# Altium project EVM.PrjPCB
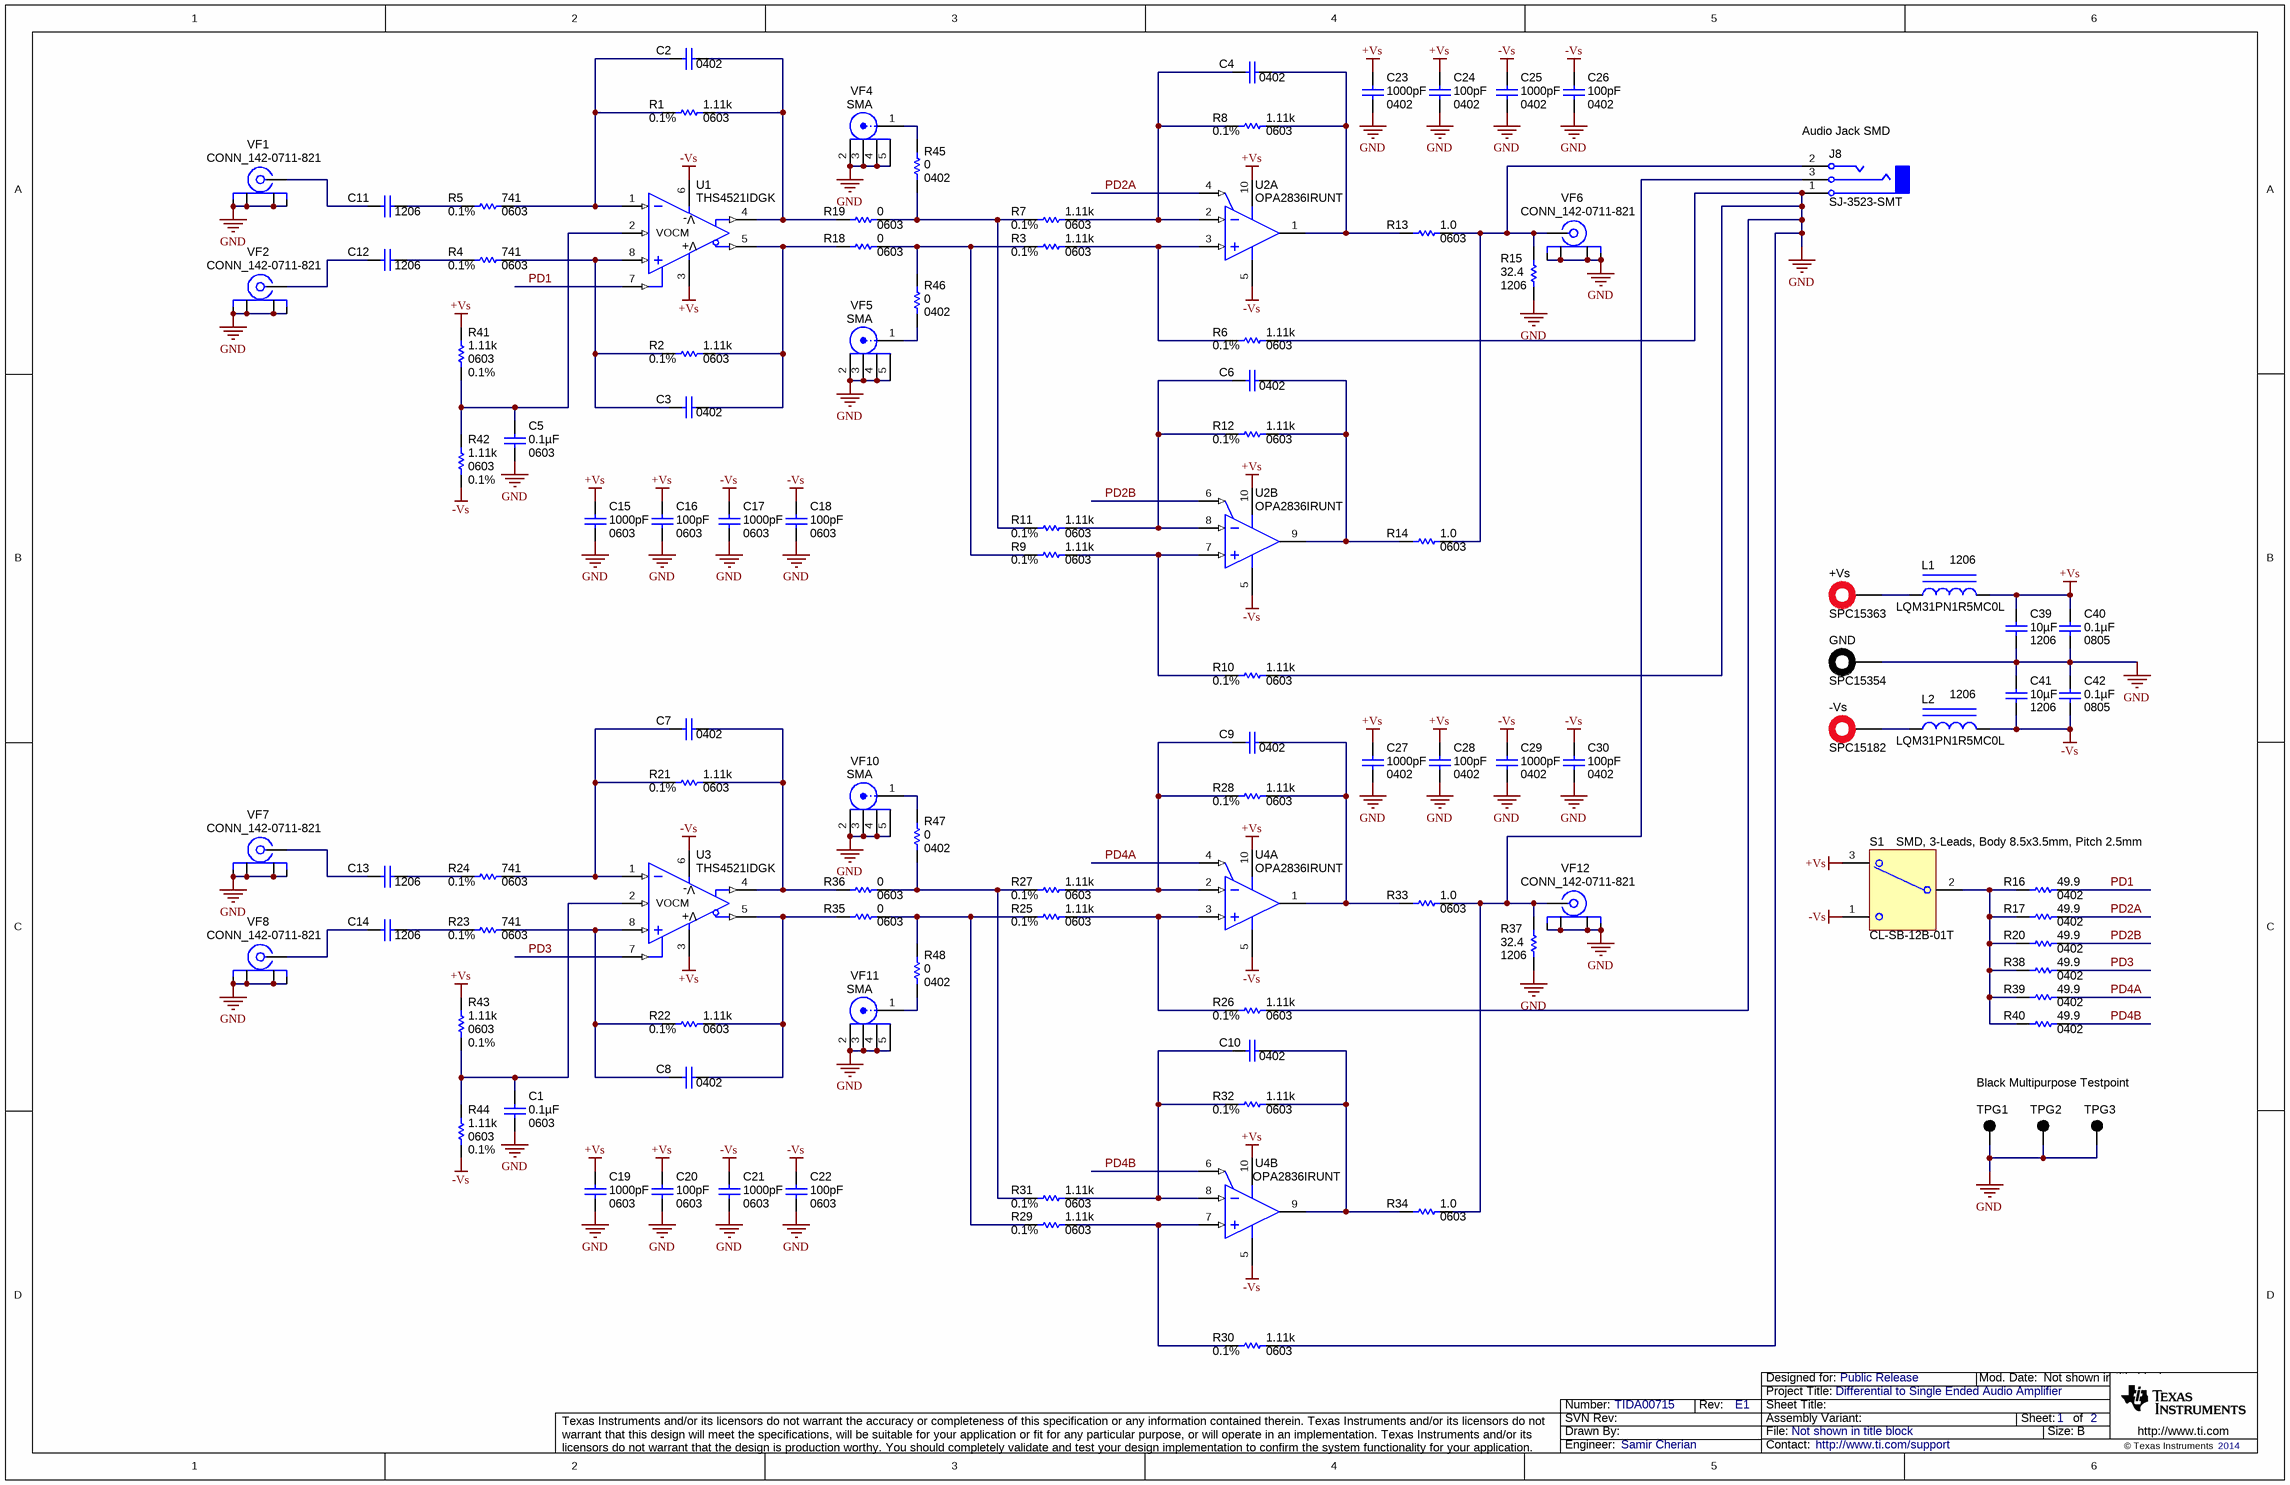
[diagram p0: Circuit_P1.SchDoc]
TechSupport: http://www.ti.com/support; SCH_Rev: E1; PRJ_Title: Differential to Single Ended Audio Amplifier; PRJ_Number: TIDA00715; PRJ_Engineer: Samir Cherian; PRJ_Customer: Public Release; PCB_Rev: E1; PCB_Layout: Bob Holtz; CopyrightYear: 2014
2 sheets, 126 parts. Net scope: global (net labels, ports and power ports of the same name join across sheets).
Board file: EVM.PcbDoc
Sheets:
  Circuit_P1.SchDoc
  Hardware_P2.SchDoc

## Sheet Circuit_P1.SchDoc
size 431 x 279 mm; Date: Not shown in title block; ApprovedBy: Not shown in title block; CheckedBy: Not shown in title block; Author: Not shown in title block; CompanyName: Not shown in title block; Engineer: Not shown in title block; Organization: Not shown in title block; Address1: Not shown in title block; Address2: Not shown in title block; Address3: Not shown in title block; Address4: Not shown in title block; DocumentNumber: 1; Revision: Use project parameter SCH_Rev; SheetNumber: 1; SheetTotal: 2; PageSetup: Record=PageOptions¦CenterHorizontal=True¦CenterVertical=True¦PrintScale=0.64¦XCorrection=1.00¦YCorrection=1.00¦PrintKind=0¦BorderSize=5000000¦LeftOffset=0¦BottomOffset=0¦Orientation=2¦PaperLength=1000¦PaperWidth=1000¦Scale=100¦PaperSource=15¦PrintQuality=600¦MediaType=1¦DitherType=10¦PrintScaleMode=1¦PaperKind=Letter

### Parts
+Vs  SPC15363  [Tenma_SPC15363]
-Vs  SPC15182  [Tenma_SPC15363]
C1  ValueDisplayed: 0.1µF  PackageReference: 0603  [0603L]  (hidden comment: C1608X7R1H104K)
C2  PackageReference: 0402  [0402L]
C3  PackageReference: 0402  [0402L]
C4  PackageReference: 0402  [0402L]
C5  ValueDisplayed: 0.1µF  PackageReference: 0603  [0603L]  (hidden comment: C1608X7R1H104K)
C6  PackageReference: 0402  [0402L]
C7  PackageReference: 0402  [0402L]
C8  PackageReference: 0402  [0402L]
C9  PackageReference: 0402  [0402L]
C10  PackageReference: 0402  [0402L]
C11  PackageReference: 1206  [1206L]
C12  PackageReference: 1206  [1206L]
C13  PackageReference: 1206  [1206L]
C14  PackageReference: 1206  [1206L]
C15  ValueDisplayed: 1000pF  PackageReference: 0603  [0603L]  (hidden comment: C1608C0G1H102J)
C16  ValueDisplayed: 100pF  PackageReference: 0603  [0603L]  (hidden comment: 06035A101JAT2A)
C17  ValueDisplayed: 1000pF  PackageReference: 0603  [0603L]  (hidden comment: C1608C0G1H102J)
C18  ValueDisplayed: 100pF  PackageReference: 0603  [0603L]  (hidden comment: 06035A101JAT2A)
C19  ValueDisplayed: 1000pF  PackageReference: 0603  [0603L]  (hidden comment: C1608C0G1H102J)
C20  ValueDisplayed: 100pF  PackageReference: 0603  [0603L]  (hidden comment: 06035A101JAT2A)
C21  ValueDisplayed: 1000pF  PackageReference: 0603  [0603L]  (hidden comment: C1608C0G1H102J)
C22  ValueDisplayed: 100pF  PackageReference: 0603  [0603L]  (hidden comment: 06035A101JAT2A)
C23  ValueDisplayed: 1000pF  PackageReference: 0402  [0402L]  (hidden comment: C1005C0G1E102J)
C24  ValueDisplayed: 100pF  PackageReference: 0402  [0402L]  (hidden comment: CC0402JRNPO9BN101)
C25  ValueDisplayed: 1000pF  PackageReference: 0402  [0402L]  (hidden comment: C1005C0G1E102J)
C26  ValueDisplayed: 100pF  PackageReference: 0402  [0402L]  (hidden comment: CC0402JRNPO9BN101)
C27  ValueDisplayed: 1000pF  PackageReference: 0402  [0402L]  (hidden comment: C1005C0G1E102J)
C28  ValueDisplayed: 100pF  PackageReference: 0402  [0402L]  (hidden comment: CC0402JRNPO9BN101)
C29  ValueDisplayed: 1000pF  PackageReference: 0402  [0402L]  (hidden comment: C1005C0G1E102J)
C30  ValueDisplayed: 100pF  PackageReference: 0402  [0402L]  (hidden comment: CC0402JRNPO9BN101)
C39  ValueDisplayed: 10µF  PackageReference: 1206  [1206L]  (hidden comment: GRM31CR61E106KA12L)
C40  ValueDisplayed: 0.1µF  PackageReference: 0805  [0805L]  (hidden comment: 08055C104KAT2A)
C41  ValueDisplayed: 10µF  PackageReference: 1206  [1206L]  (hidden comment: GRM31CR61E106KA12L)
C42  ValueDisplayed: 0.1µF  PackageReference: 0805  [0805L]  (hidden comment: 08055C104KAT2A)
GND  SPC15354  [Tenma_SPC15354]
J8  SJ-3523-SMT  PackageReference: Audio Jack SMD  [CUI_SJ-3523-SMT]
L1  LQM31PN1R5MC0L  PackageReference: 1206  [1206L]
L2  LQM31PN1R5MC0L  PackageReference: 1206  [1206L]
R1  ValueDisplayed: 1.11k  PackageReference: 0603  Value1: 0.1%  [0603L]  (hidden comment: RT0603BRD071K11L)
R2  ValueDisplayed: 1.11k  PackageReference: 0603  Value1: 0.1%  [0603L]  (hidden comment: RT0603BRD071K11L)
R3  ValueDisplayed: 1.11k  PackageReference: 0603  Value1: 0.1%  [0603L]  (hidden comment: RT0603BRD071K11L)
R4  ValueDisplayed: 741  PackageReference: 0603  Value1: 0.1%  [0603L]  (hidden comment: RT0603BRD07741RL)
R5  ValueDisplayed: 741  PackageReference: 0603  Value1: 0.1%  [0603L]  (hidden comment: RT0603BRD07741RL)
R6  ValueDisplayed: 1.11k  PackageReference: 0603  Value1: 0.1%  [0603L]  (hidden comment: RT0603BRD071K11L)
R7  ValueDisplayed: 1.11k  PackageReference: 0603  Value1: 0.1%  [0603L]  (hidden comment: RT0603BRD071K11L)
R8  ValueDisplayed: 1.11k  PackageReference: 0603  Value1: 0.1%  [0603L]  (hidden comment: RT0603BRD071K11L)
R9  ValueDisplayed: 1.11k  PackageReference: 0603  Value1: 0.1%  [0603L]  (hidden comment: RT0603BRD071K11L)
R10  ValueDisplayed: 1.11k  PackageReference: 0603  Value1: 0.1%  [0603L]  (hidden comment: RT0603BRD071K11L)
R11  ValueDisplayed: 1.11k  PackageReference: 0603  Value1: 0.1%  [0603L]  (hidden comment: RT0603BRD071K11L)
R12  ValueDisplayed: 1.11k  PackageReference: 0603  Value1: 0.1%  [0603L]  (hidden comment: RT0603BRD071K11L)
R13  ValueDisplayed: 1.0  PackageReference: 0603  [0603L]  (hidden comment: CRCW06031R00JNEA)
R14  ValueDisplayed: 1.0  PackageReference: 0603  [0603L]  (hidden comment: CRCW06031R00JNEA)
R15  ValueDisplayed: 32.4  PackageReference: 1206  [1206L]  (hidden comment: CRCW120632R4FKEA)
R16  ValueDisplayed: 49.9  PackageReference: 0402  [0402L]  (hidden comment: CRCW040249R9FKED)
R17  ValueDisplayed: 49.9  PackageReference: 0402  [0402L]  (hidden comment: CRCW040249R9FKED)
R18  ValueDisplayed: 0  PackageReference: 0603  [0603L]  (hidden comment: CRCW06030000Z0EA)
R19  ValueDisplayed: 0  PackageReference: 0603  [0603L]  (hidden comment: CRCW06030000Z0EA)
R20  ValueDisplayed: 49.9  PackageReference: 0402  [0402L]  (hidden comment: CRCW040249R9FKED)
R21  ValueDisplayed: 1.11k  PackageReference: 0603  Value1: 0.1%  [0603L]  (hidden comment: RT0603BRD071K11L)
R22  ValueDisplayed: 1.11k  PackageReference: 0603  Value1: 0.1%  [0603L]  (hidden comment: RT0603BRD071K11L)
R23  ValueDisplayed: 741  PackageReference: 0603  Value1: 0.1%  [0603L]  (hidden comment: RT0603BRD07741RL)
R24  ValueDisplayed: 741  PackageReference: 0603  Value1: 0.1%  [0603L]  (hidden comment: RT0603BRD07741RL)
R25  ValueDisplayed: 1.11k  PackageReference: 0603  Value1: 0.1%  [0603L]  (hidden comment: RT0603BRD071K11L)
R26  ValueDisplayed: 1.11k  PackageReference: 0603  Value1: 0.1%  [0603L]  (hidden comment: RT0603BRD071K11L)
R27  ValueDisplayed: 1.11k  PackageReference: 0603  Value1: 0.1%  [0603L]  (hidden comment: RT0603BRD071K11L)
R28  ValueDisplayed: 1.11k  PackageReference: 0603  Value1: 0.1%  [0603L]  (hidden comment: RT0603BRD071K11L)
R29  ValueDisplayed: 1.11k  PackageReference: 0603  Value1: 0.1%  [0603L]  (hidden comment: RT0603BRD071K11L)
R30  ValueDisplayed: 1.11k  PackageReference: 0603  Value1: 0.1%  [0603L]  (hidden comment: RT0603BRD071K11L)
R31  ValueDisplayed: 1.11k  PackageReference: 0603  Value1: 0.1%  [0603L]  (hidden comment: RT0603BRD071K11L)
R32  ValueDisplayed: 1.11k  PackageReference: 0603  Value1: 0.1%  [0603L]  (hidden comment: RT0603BRD071K11L)
R33  ValueDisplayed: 1.0  PackageReference: 0603  [0603L]  (hidden comment: CRCW06031R00JNEA)
R34  ValueDisplayed: 1.0  PackageReference: 0603  [0603L]  (hidden comment: CRCW06031R00JNEA)
R35  ValueDisplayed: 0  PackageReference: 0603  [0603L]  (hidden comment: CRCW06030000Z0EA)
R36  ValueDisplayed: 0  PackageReference: 0603  [0603L]  (hidden comment: CRCW06030000Z0EA)
R37  ValueDisplayed: 32.4  PackageReference: 1206  [1206L]  (hidden comment: CRCW120632R4FKEA)
R38  ValueDisplayed: 49.9  PackageReference: 0402  [0402L]  (hidden comment: CRCW040249R9FKED)
R39  ValueDisplayed: 49.9  PackageReference: 0402  [0402L]  (hidden comment: CRCW040249R9FKED)
R40  ValueDisplayed: 49.9  PackageReference: 0402  [0402L]  (hidden comment: CRCW040249R9FKED)
R41  ValueDisplayed: 1.11k  PackageReference: 0603  Value1: 0.1%  [0603L]  (hidden comment: RT0603BRD071K11L)
R42  ValueDisplayed: 1.11k  PackageReference: 0603  Value1: 0.1%  [0603L]  (hidden comment: RT0603BRD071K11L)
R43  ValueDisplayed: 1.11k  PackageReference: 0603  Value1: 0.1%  [0603L]  (hidden comment: RT0603BRD071K11L)
R44  ValueDisplayed: 1.11k  PackageReference: 0603  Value1: 0.1%  [0603L]  (hidden comment: RT0603BRD071K11L)
R45  ValueDisplayed: 0  PackageReference: 0402  [0402L]  (hidden comment: CRCW04020000Z0ED)
R46  ValueDisplayed: 0  PackageReference: 0402  [0402L]  (hidden comment: CRCW04020000Z0ED)
R47  ValueDisplayed: 0  PackageReference: 0402  [0402L]  (hidden comment: CRCW04020000Z0ED)
R48  ValueDisplayed: 0  PackageReference: 0402  [0402L]  (hidden comment: CRCW04020000Z0ED)
S1  CL-SB-12B-01T  PackageReference: SMD, 3-Leads, Body 8.5x3.5mm, Pitch 2.5mm  [SW_CL-SB-12B-01]
TPG1  5011  [Keystone5011]  (value not drawn)
TPG2  PackageReference: Black Multipurpose Testpoint  [Keystone5011]  (hidden comment: 5011)
TPG3  5011  [Keystone5011]  (value not drawn)
U1  THS4521IDGK  [DGK0008A_N]
U2  OPA2836IRUNT  [RUN0010A]  (parts A,B of 2)
U3  THS4521IDGK  [DGK0008A_N]
U4  OPA2836IRUNT  [RUN0010A]  (parts A,B of 2)
VF1  CONN_142-0711-821  [CONN_142-0711-821]
VF2  CONN_142-0711-821  [CONN_142-0711-821]
VF4  PackageReference: SMA  [Johnson_142-0701-20x]  (hidden comment: 142-0701-201)
VF5  PackageReference: SMA  [Johnson_142-0701-20x]  (hidden comment: 142-0701-201)
VF6  CONN_142-0711-821  [CONN_142-0711-821]
VF7  CONN_142-0711-821  [CONN_142-0711-821]
VF8  CONN_142-0711-821  [CONN_142-0711-821]
VF10  PackageReference: SMA  [Johnson_142-0701-20x]  (hidden comment: 142-0701-201)
VF11  PackageReference: SMA  [Johnson_142-0701-20x]  (hidden comment: 142-0701-201)
VF12  CONN_142-0711-821  [CONN_142-0711-821]

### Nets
+Vs: C15.1 C16.1 C19.1 C20.1 C23.1 C24.1 C27.1 C28.1 C39.1 C40.1 L1.2 R41.2 R43.2 S1.3 U1.3(VS+) U2.10(VS+) U3.3(VS+) U4.10(VS+)
-Vs: C17.1 C18.1 C21.1 C22.1 C25.1 C26.1 C29.1 C30.1 C41.2 C42.2 L2.2 R42.1 R44.1 S1.1 U1.6(VS-) U2.5(VS-) U3.6(VS-) U4.5(VS-)
GND: C1.2 C5.2 C15.2 C16.2 C17.2 C18.2 C19.2 C20.2 C21.2 C22.2 C23.2 C24.2 C25.2 C26.2 C27.2 C28.2 C29.2 C30.2 C39.2 C40.2 C41.1 C42.1 GND.1 J8.1(SLEEVE) R6.2 R10.2 R15.1 R26.2 R30.2 R37.1 TPG1.1 TPG2.1 TPG3.1 VF1.2(GND) VF1.3(GND) VF1.4 VF1.5(GND) VF2.2(GND) VF2.3(GND) VF2.4 VF2.5(GND) VF4.2 VF4.3 VF4.4 VF4.5 VF5.2 VF5.3 VF5.4 VF5.5 VF6.2(GND) VF6.3(GND) VF6.4 VF6.5(GND) VF7.2(GND) VF7.3(GND) VF7.4 VF7.5(GND) VF8.2(GND) VF8.3(GND) VF8.4 VF8.5(GND) VF10.2 VF10.3 VF10.4 VF10.5 VF11.2 VF11.3 VF11.4 VF11.5 VF12.2(GND) VF12.3(GND) VF12.4 VF12.5(GND)
PD1: R16.2 U1.7(~{PD})
PD2A: R17.2 U2.4(~{PD1})
PD2B: R20.2 U2.6(~{PD2})
PD3: R38.2 U3.7(~{PD})
PD4A: R39.2 U4.4(~{PD1})
PD4B: R40.2 U4.6(~{PD2})
Net+Vs_1: +Vs.1 L1.1
Net-Vs_1: -Vs.1 L2.1
NetC1_1: C1.1 R43.1 R44.2 U3.2(VOCM)
NetC2_1: C2.1 R1.2 R19.1 U1.4(VOUT+)
NetC2_2: C2.2 R1.1 R5.2 U1.1(VIN-)
NetC3_1: C3.1 R2.2 R18.1 U1.5(VOUT-)
NetC3_2: C3.2 R2.1 R4.2 U1.8(VIN+)
NetC4_1: C4.1 R8.2 R13.1 U2.1(VOUT1)
NetC4_2: C4.2 R7.2 R8.1 U2.2(VIN1-)
NetC5_1: C5.1 R41.1 R42.2 U1.2(VOCM)
NetC6_1: C6.1 R12.2 R14.1 U2.9(VOUT2)
NetC6_2: C6.2 R11.2 R12.1 U2.8(VIN2-)
NetC7_1: C7.1 R21.2 R36.1 U3.4(VOUT+)
NetC7_2: C7.2 R21.1 R24.2 U3.1(VIN-)
NetC8_1: C8.1 R22.2 R35.1 U3.5(VOUT-)
NetC8_2: C8.2 R22.1 R23.2 U3.8(VIN+)
NetC9_1: C9.1 R28.2 R33.1 U4.1(VOUT1)
NetC9_2: C9.2 R27.2 R28.1 U4.2(VIN1-)
NetC10_1: C10.1 R32.2 R34.1 U4.9(VOUT2)
NetC10_2: C10.2 R31.2 R32.1 U4.8(VIN2-)
NetC11_1: C11.1 R5.1
NetC11_2: C11.2 VF1.1(SIGNAL)
NetC12_1: C12.1 R4.1
NetC12_2: C12.2 VF2.1(SIGNAL)
NetC13_1: C13.1 R24.1
NetC13_2: C13.2 VF7.1(SIGNAL)
NetC14_1: C14.1 R23.1
NetC14_2: C14.2 VF8.1(SIGNAL)
NetJ8_2: J8.2(TIP) R13.2 R14.2 R15.2 VF6.1(SIGNAL)
NetJ8_3: J8.3(RING) R33.2 R34.2 R37.2 VF12.1(SIGNAL)
NetR3_1: R3.1 R9.1 R18.2 R46.2
NetR3_2: R3.2 R6.1 U2.3(VIN1+)
NetR7_1: R7.1 R11.1 R19.2 R45.1
NetR9_2: R9.2 R10.1 U2.7(VIN2+)
NetR16_1: R16.1 R17.1 R20.1 R38.1 R39.1 R40.1 S1.2(COM)
NetR25_1: R25.1 R29.1 R35.2 R48.2
NetR25_2: R25.2 R26.1 U4.3(VIN1+)
NetR27_1: R27.1 R31.1 R36.2 R47.1
NetR29_2: R29.2 R30.1 U4.7(VIN2+)
NetR45_2: R45.2 VF4.1
NetR46_1: R46.1 VF5.1
NetR47_2: R47.2 VF10.1
NetR48_1: R48.1 VF11.1

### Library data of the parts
+Vs = SPC15363: BANANA JACK, SOLDER LUG, RED, TH; Manufacturer: Tenma; SymbolCreator: a0412235; U/M: EA
-Vs = SPC15363: BANANA JACK, SOLDER LUG, GREEN, TH; Manufacturer: Tenma; SymbolCreator: a0412235; U/M: EA
C1 C5 = C1608X7R1H104K: CAP, CERM, 0.1 µF, 50 V, +/- 10%, X7R, 0603; Manufacturer: TDK; Polarized: N; CompType: Capacitor; Value: 0.1uF; U/M: EA; Cap_F: 0.0000001; Tolerance_%: 10; ESR_ohm: 0.017; Value1: 0.017 ohm; VDC_V: 50; Value2: 50V; TaMin_C: -55; TaMax_C: 125
C2-C4 C6-C14 = Capacitor: CAP, CERM, xxxF, xxV, [TempCo], xx%, [PackageReference]; Manufacturer: Used in BOM report; Polarized: N; U/M: EA
C15 C17 C19 C21 = C1608C0G1H102J: CAP, CERM, 1000 pF, 50 V, +/- 5%, C0G/NP0, 0603; Manufacturer: TDK; Polarized: N; CompType: Capacitor; Value: 1000pF; U/M: EA; Cap_F: 0.000000001; Tolerance_%: 5; ESR_ohm: 0.0563; Value1: 0.0563 ohm; VDC_V: 50; Value2: 50V; TaMin_C: -55; TaMax_C: 125
C16 C18 C20 C22 = 06035A101JAT2A: CAP, CERM, 100 pF, 50 V, +/- 5%, C0G/NP0, 0603; Manufacturer: AVX; Polarized: N; CompType: Capacitor; Value: 100pF; U/M: EA; Cap_F: 0.0000000001; Tolerance_%: 5; ESR_ohm: 0.119; Value1: 0.119 ohm; VDC_V: 50; Value2: 50V; TaMin_C: -55; TaMax_C: 125
C23 C25 C27 C29 = C1005C0G1E102J: CAP, CERM, 1000 pF, 25 V, +/- 5%, C0G/NP0, 0402; Manufacturer: TDK; Polarized: N; CompType: Capacitor; Value: 1000pF; U/M: EA; Cap_F: 0.000000001; Tolerance_%: 5; Value1: Unknown; VDC_V: 25; Value2: 25V; TaMin_C: -55; TaMax_C: 125
C24 C26 C28 C30 = CC0402JRNPO9BN101: CAP, CERM, 100 pF, 50 V, +/- 5%, C0G/NP0, 0402; Manufacturer: Yageo America; Polarized: N; CompType: Capacitor; Value: 100pF; U/M: EA; Cap_F: 0.0000000001; Tolerance_%: 5; Value1: Unknown; VDC_V: 50; Value2: 50V; TaMin_C: -55; TaMax_C: 125
C39 C41 = GRM31CR61E106KA12L: CAP, CERM, 10 µF, 25 V, +/- 10%, X5R, 1206; Manufacturer: MuRata; Polarized: N; CompType: Capacitor; Value: 10uF; U/M: EA; Cap_F: 0.00001; Tolerance_%: 10; ESR_ohm: 0.004; Value1: 0.004 ohm; VDC_V: 25; Value2: 25V; TaMin_C: -55; TaMax_C: 85
C40 C42 = 08055C104KAT2A: CAP, CERM, 0.1 µF, 50 V, +/- 10%, X7R, 0805; Manufacturer: AVX; Polarized: N; CompType: Capacitor; Value: 0.1uF; U/M: EA; Cap_F: 0.0000001; Tolerance_%: 10; ESR_ohm: 0.024; Value1: 0.024 ohm; VDC_V: 50; Value2: 50V; TaMin_C: -55; TaMax_C: 125
GND = SPC15354: BANANA JACK, SOLDER LUG, BLACK, TH; Manufacturer: Tenma; SymbolCreator: a0412235; U/M: EA
J8 = SJ-3523-SMT: Audio Jack, 3.5mm, Stereo, R/A, SMT; Manufacturer: CUI Inc.; SymbolCreator: a0412235; U/M: EA
L1 L2 = LQM31PN1R5MC0L: Inductor, Multilayer, Ferrite, 1.5 µH, 1 A, 0.17 ohm, SMD; Manufacturer: MuRata; Value: 1.5uH; Ind_H: 1.5E-6; ValueDisplayed: 1.5µH; Imax_A: 1; Irms: 1A @ 40C rise; DCR_ohm: 0.17; Value2: 1A
R1-R3 R6-R12 R21 R22 R25-R32 R41-R44 = RT0603BRD071K11L: RES, 1.11 k, 0.1%, 0.1 W, 0603; Manufacturer: Yageo America; CompType: Resistor; Value: 1.11k; Res_ohm: 1110; Value_Code: 1k11; Tolerance_%: 0.1; Value2: 0.1W; VDC_V: 75; TempCo: 25 ppm/C; EIA_Code: E192; U/M: EA
R4 R5 R23 R24 = RT0603BRD07741RL: RES, 741, 0.1%, 0.1 W, 0603; Manufacturer: Yageo America; CompType: Resistor; Value: 741; Value_Code: 741R; Tolerance_%: 0.1; Value2: 0.1W; VDC_V: 75; TempCo: 25 ppm/C; EIA_Code: E192; U/M: EA
R13 R14 R33 R34 = CRCW06031R00JNEA: RES, 1.0, 5%, 0.1 W, 0603; Manufacturer: Vishay-Dale; CompType: Resistor; Value: 1.0; Res_ohm: 1; Value_Code: 1R00; Tolerance_%: 5; Power_W: 0.1; Value2: 0.1W; VDC_V: 75; TempCo: 200 ppm/C; EIA_Code: E24; U/M: EA
R15 R37 = CRCW120632R4FKEA: RES, 32.4, 1%, 0.25 W, 1206; Manufacturer: Vishay-Dale; CompType: Resistor; Value: 32.4; Value_Code: 32R4; Tolerance_%: 1; Power_W: 0.25; Value2: 0.25W; VDC_V: 200; TempCo: 100 ppm/C; EIA_Code: E96; U/M: EA
R16 R17 R20 R38-R40 = CRCW040249R9FKED: RES, 49.9, 1%, 0.063 W, 0402; Manufacturer: Vishay-Dale; CompType: Resistor; Value: 49.9; Value_Code: 49R9; Tolerance_%: 1; Power_W: 0.063; Value2: 0.063W; VDC_V: 50; TempCo: 100 ppm/C; EIA_Code: E96; U/M: EA
R18 R19 R35 R36 = CRCW06030000Z0EA: RES, 0, 5%, 0.1 W, 0603; Manufacturer: Vishay-Dale; CompType: Resistor; Value: 0; Value_Code: 0000; Tolerance_%: 5; Power_W: 0.1; Value2: 0.1W; VDC_V: 75; TempCo: 200 ppm/C; EIA_Code: E24; U/M: EA
R45-R48 = CRCW04020000Z0ED: RES, 0, 5%, 0.063 W, 0402; Manufacturer: Vishay-Dale; CompType: Resistor; Value: 0; Value_Code: 0000; Tolerance_%: 5; Power_W: 0.063; Value2: 0.063W; VDC_V: 50; TempCo: 200 ppm/C; EIA_Code: E24; U/M: EA
S1 = CL-SB-12B-01T: Switch, Slide, SPDT, 0.2A, GULL, 12V, SMD; Manufacturer: Copal Electronics; SymbolCreator: x0208326; VDC_V: 12; SwitchFunction: On-On; PositionCount: 2; CurrentRating_mA: 200
TPG1-TPG3 = 5011: Test Point, Multipurpose, Black, TH; Manufacturer: Keystone; CompType: Test Point Loop; U/M: EA
U1 U3 = THS4521IDGK: VERY LOW POWER, NEGATIVE RAIL INPUT, RAIL-TO-RAIL OUTPUT, FULLY DIFFERENTIAL AMPLIFIER, DGK0008A; Manufacturer: Texas Instruments; SymbolCreator: a0411947; CompType: IC; U/M: EA
U2 U4 = OPA2836IRUNT: Dual, Very Low Power, Rail to Rail Out, Negative Rail In, VFB Operational Amplifier, 2.5 to 5.5 V, -40 to 85 degC, 10-pin QFN (RUN0010A), Green (RoHS & no Sb/Br); Manufacturer: Texas Instruments; Alternate Manufacturer: None; Alternate PartNumber: Equivalent; 2nd Harmonic(dBc): 85; 3rd Harmonic(dBc): 105; Acl, min stable gain(V/V): 1; BW @ Acl(MHz): 205; Iib(Max)(nA): 1550; Io(Typ)(mA): 50; Iq per channel(Max)(mA): 1.2; Number of Channels: 2; Settling Time (0.1%)(Typ)(ns): 30; Slew Rate(Typ)(V/us): 560; Sub Family: High Output Current Amplifier (>=50mA), High Speed Amplifier (>=50MHz), Low Noise Amp (<=10nV/rtHz), Low Offset Voltage Amplifier (<=500uV), Low Supply Voltage Amplifier (<=2.7V); THD (Fc is 1 MHz)(Typ)(dB): -130; Vio(Max)(mV): 0.4; Vn at Flatband(Typ)(nV/rtHz): 4.6; Vs(Max)(V): 5.5; Vs(Min)(V): 2.5
VF1 VF2 VF6-VF8 VF12 = CONN_142-0711-821: CONNECTOR, SHEILDED, END LAUNCH JACK, GOLD PLATED, FOR 0.062 PCB, EDGE MOUNTED; Manufacturer: Cinch Connectivity Solutions Johnson; area: 95000
VF4 VF5 VF10 VF11 = 142-0701-201: Connector, TH, SMA; Manufacturer: Emerson Network Power; SymbolCreator: X0208326; U/M: EA

## Sheet Hardware_P2.SchDoc
size 431 x 279 mm; Date: Not shown in title block; ApprovedBy: Not shown in title block; CheckedBy: Not shown in title block; Author: Not shown in title block; CompanyName: Not shown in title block; Engineer: Not shown in title block; Organization: Not shown in title block; Address1: Not shown in title block; Address2: Not shown in title block; Address3: Not shown in title block; Address4: Not shown in title block; DocumentNumber: 2; Revision: Use project parameter SCH_Rev; SheetNumber: 2; SheetTotal: 2; PageSetup: Record=PageOptions¦CenterHorizontal=True¦CenterVertical=True¦PrintScale=1.00¦XCorrection=1.00¦YCorrection=1.00¦PrintKind=0¦BorderSize=5000000¦LeftOffset=0¦BottomOffset=0¦Orientation=2¦PaperLength=1000¦PaperWidth=1000¦Scale=100¦PaperSource=15¦PrintQuality=600¦MediaType=1¦DitherType=10¦PaperKind=Letter¦PrintScaleMode=1
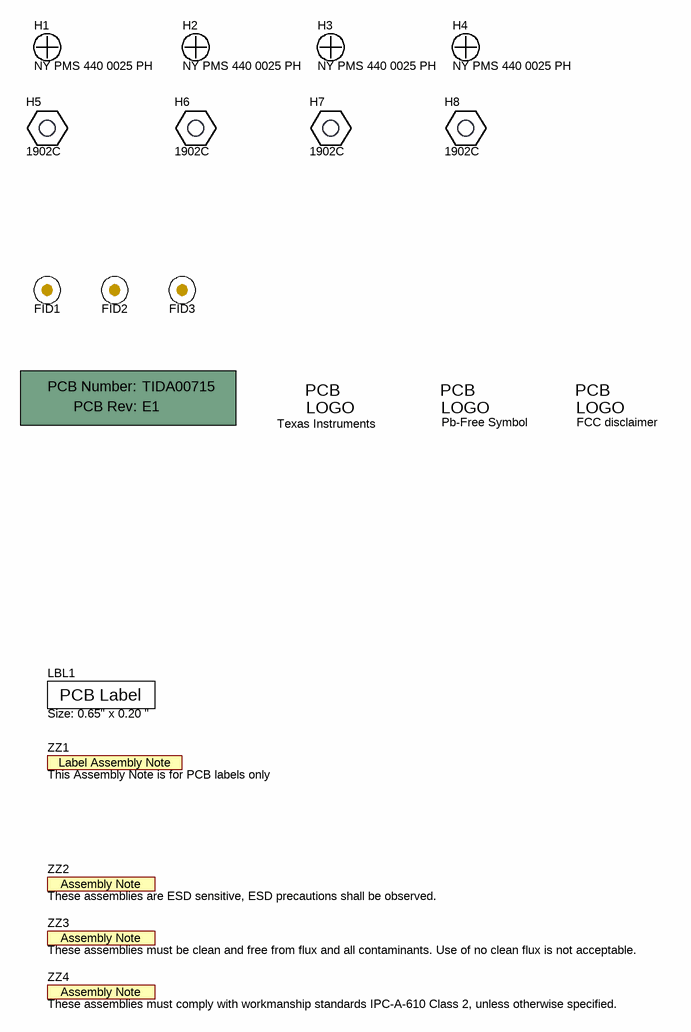
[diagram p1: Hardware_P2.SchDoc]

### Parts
!PCB  Printed Circuit Board  (value not drawn)  (mechanical)
FID1  Fiducial  [Fiducial10-20]  (value not drawn)
FID2  Fiducial  [Fiducial10-20]  (value not drawn)
FID3  Fiducial  [Fiducial10-20]  (value not drawn)
H1  NY PMS 440 0025 PH  [NY PMS 440 0025 PH]
H2  NY PMS 440 0025 PH  [NY PMS 440 0025 PH]
H3  NY PMS 440 0025 PH  [NY PMS 440 0025 PH]
H4  NY PMS 440 0025 PH  [NY PMS 440 0025 PH]
H5  1902C  [Keystone_1902C]
H6  1902C  [Keystone_1902C]
H7  1902C  [Keystone_1902C]
H8  1902C  [Keystone_1902C]
LBL1  Size: 0.65" x 0.20 "  [Label_650x200]
Logo1  Texas Instruments  [TI_Stacked_Overlay_Small]  (no BOM)
Logo2  Pb-Free Symbol  [Pb-Free_Overlay_Small]  (no BOM)
Logo3  FCC disclaimer  [FCC_disclaimer]  (no BOM)
ZZ1  This Assembly Note is for PCB labels only  [AssemblyNoteLabel]  (no BOM)
ZZ2  These assemblies are ESD sensitive, ESD precautions shall be observed.  [AssemblyNote]  (no BOM)
ZZ3  These assemblies must be clean and free from flux and all contaminants. Use of no clean flux is not acceptable.  [AssemblyNote]  (no BOM)
ZZ4  These assemblies must comply with workmanship standards IPC-A-610 Class 2, unless otherwise specified.  [AssemblyNote]  (no BOM)

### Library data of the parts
!PCB = PCB: Manufacturer: Any; PartNumber: TIDA00715; SymbolCreator: a0412235
FID1-FID3 = Fiducial: Fiducial mark.  There is nothing to buy or mount.; SymbolCreator: codlsc
H1-H4 = NY PMS 440 0025 PH: Machine Screw, Round, #4-40 x 1/4, Nylon, Philips panhead; Manufacturer: B&F Fastener Supply; CompType: Hardware; SymbolCreator: codlsc; U/M: EA
H5-H8 = 1902C: Standoff, Hex, 0.5"L #4-40 Nylon; Manufacturer: Keystone; CompType: Hardware; SymbolCreator: a0412235
LBL1 = THT-14-423-10: Thermal Transfer Printable Labels, 0.650" W x 0.200" H - 10,000 per roll; Manufacturer: Brady; SymbolCreator: a0412235; CompType: Label
Logo1 = TI_Logo: Texas Instrument Corporate Signature; SymbolCreator: a0412235
Logo2 = Pb-Free: SymbolCreator: a0412235
Logo3 = FCC_disclaimer: SymbolCreator: codlsc
ZZ1 = AssemblyNoteLabel: SymbolCreator: a0412235
ZZ2-ZZ4 = AssemblyNote: SymbolCreator: codlsc

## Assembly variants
001: not fitted C2 C3 C4 C6 C7 C8 C9 C10 FID1 FID2 FID3 R41 R42 R43 R44 R45 R46 R47 R48 TPG1 TPG2 TPG3 VF4 VF5 VF10 VF11; alternate parts R4 -> RT0603BRD07698RL, R5 -> RT0603BRD07698RL, R6 -> RT0603BRD07732RL, R8 -> RT0603BRD07732RL, R10 -> RT0603BRD07732RL, R12 -> RT0603BRD07732RL, R23 -> RT0603BRD07698RL, R24 -> RT0603BRD07698RL, R26 -> RT0603BRD07732RL, R28 -> RT0603BRD07732RL, R30 -> RT0603BRD07732RL, R32 -> RT0603BRD07732RL, R11 -> RT0603BRD071K1L, R31 -> RT0603BRD071K1L, R29 -> RT0603BRD071K1L, R27 -> RT0603BRD071K1L, R25 -> RT0603BRD071K1L, R22 -> RT0603BRD071K1L, R21 -> RT0603BRD071K1L, R7 -> RT0603BRD071K1L, R9 -> RT0603BRD071K1L, R1 -> RT0603BRD071K1L, R2 -> RT0603BRD071K1L, R3 -> RT0603BRD071K1L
